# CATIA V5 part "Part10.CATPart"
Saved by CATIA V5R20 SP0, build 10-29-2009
Part number: 1DIN7984616_DIN 7984 - M6 x 16 --- 16C
Revision: ANY
Definition: UNKNOWN
Nomenclature: 1DIN7984616_DIN 7984 - M6 x 16 --- 16C
Source: Unknown
Bounding box of the stored display mesh (mm): x 0 to 20, y -5 to 5, z -5 to 5
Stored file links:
  C:\Users\Utente\Desktop\IO LAVORO\3D X SITO CF\CUMSA\3D files PW\pw101830\pw101830_injection\Part10.CATPart
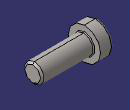
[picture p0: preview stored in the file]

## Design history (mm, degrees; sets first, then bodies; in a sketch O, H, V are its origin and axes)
Body1 "Hex" (main body)
  Solid1: solid without history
